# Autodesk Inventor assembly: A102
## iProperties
Author: Administrator
Revision Number: B
Shininess: 50.0
PropertySet Name: _Private Model Information
Created: 2000-11
Part Number: A102
Project: ACME
Description: ASSY, CLAMP SCREW
Document SubType Name: Assembly
Designer: E. MOSS
Control State: 0
Master: False
Checked Out: False
PropertySet Name: Design Tracking Control
Density: 0.0
Volumn: 0.0
Area: 0.0
PropertySet Name: Model Information
